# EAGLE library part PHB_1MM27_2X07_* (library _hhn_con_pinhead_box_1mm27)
Pin Header Box-Type, 1.27mm/0.5"/50mil Pitch, 2x07 Circuits Note: see library description for an important note about THT-version
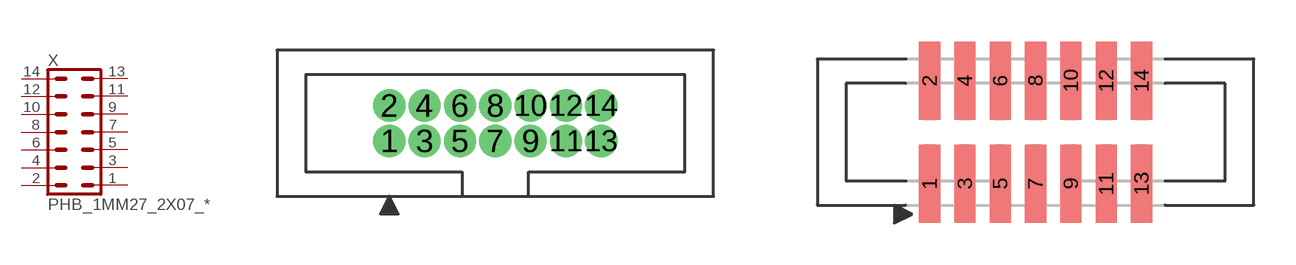
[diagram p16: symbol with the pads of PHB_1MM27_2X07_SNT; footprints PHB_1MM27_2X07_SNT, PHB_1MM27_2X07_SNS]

Designator prefix X

## PHB_1MM27_2X07_SNT  [PHB_1MM27_2X07_SNT]
1  1  pas
2  2  pas
3  3  pas
4  4  pas
5  5  pas
6  6  pas
7  7  pas
8  8  pas
9  9  pas
10  10  pas
11  11  pas
12  12  pas
13  13  pas
14  14  pas

## PHB_1MM27_2X07_SNS  [PHB_1MM27_2X07_SNS]
Pads as for PHB_1MM27_2X07_SNT

## Footprint PHB_1MM27_2X07_SNT (pad centres in mm)
Pin Header Box-Type, 1.27mm Pitch, 2x07 circuits, Straight, No Locking, THT Important Note: Diameter in this lbr is set to a specific value (NOT 'auto' = 0), this is ignored by actual eagle versions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
drill 0.65 pad 1 round: 1 -3.81,-0.635; 2 -3.81,0.635; 3 -2.54,-0.635; 4 -2.54,0.635; 5 -1.27,-0.635; 6 -1.27,0.635; 7 0,-0.635; 8 0,0.635; 9 1.27,-0.635; 10 1.27,0.635; 11 2.54,-0.635; 12 2.54,0.635; 13 3.81,-0.635; 14 3.81,0.635

## Footprint PHB_1MM27_2X07_SNS (pad centres in mm)
Pin Header Box-Type, 1.27mm Pitch, 2x07 circuits, Straight, No Locking, SMT
smd 0.76 x 2.8: 1 -3.81,-1.85; 2 -3.81,1.85; 3 -2.54,-1.85; 4 -2.54,1.85; 5 -1.27,-1.85; 6 -1.27,1.85; 7 0,-1.85; 8 0,1.85; 9 1.27,-1.85; 10 1.27,1.85; 11 2.54,-1.85; 12 2.54,1.85; 13 3.81,-1.85; 14 3.81,1.85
